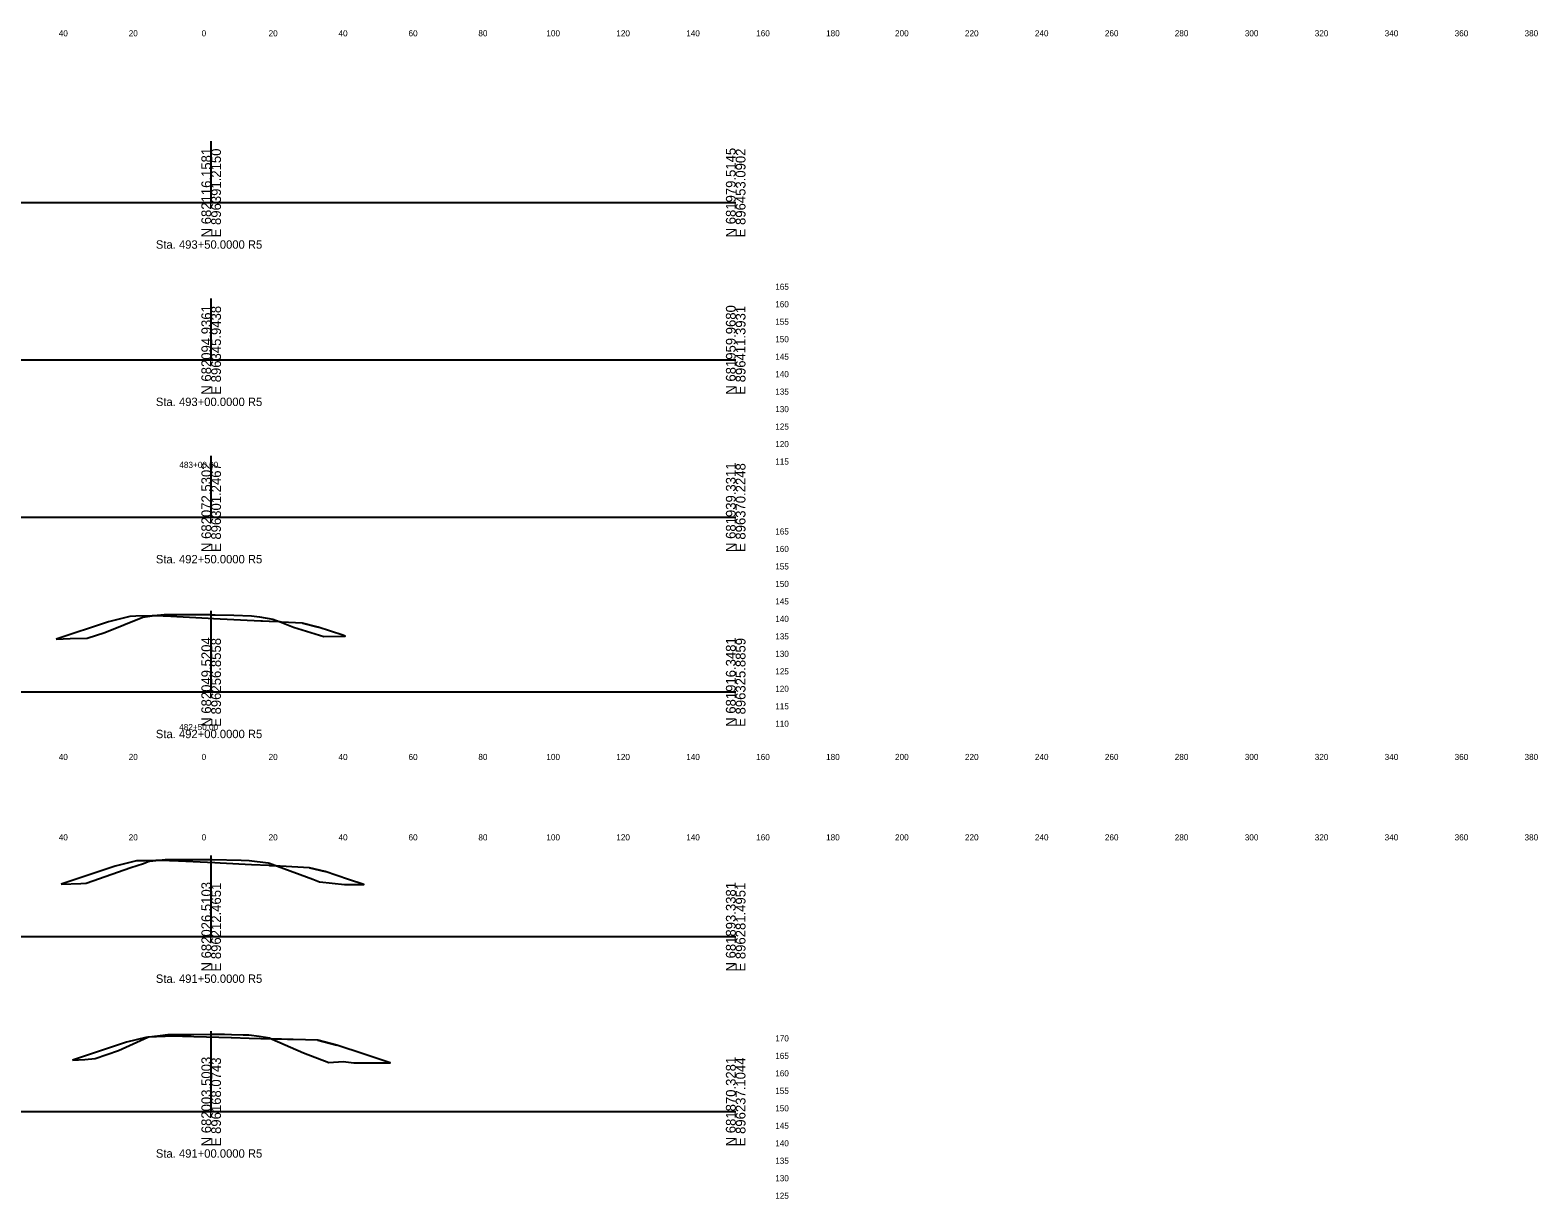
# Model space of a CAD drawing. Extents: x 21059 to 22955, y 6470 to 17494.
# Drawn here: x 21593.1 to 22024.2, y 13019.8 to 13354.1 of the extents above; entities that cross this region are included whole.
import ezdxf

# ---------------------------------------------------------------- set-up
doc = ezdxf.new("R2010")
doc.units = 0
for name, color, linetype in [('Draft_XS_Grid', 7, 'Continuous'), ('Draft_XS_Text', 7, 'Continuous'), ('DTM CONTOURS_MAJOR', 7, 'Continuous'), ('SLOPE_STAKES_FILL', 7, 'Continuous'), ('X_PROFILES_1', 7, 'Continuous'), ('XS_P_GROUND_B', 7, 'Continuous'), ('XS_P_TX_CLEARZONE', 7, 'Continuous'), ('XS_SHEET_EW_TX_VOLUME', 7, 'Continuous')]:
    doc.layers.add(name, color=color, linetype=linetype)

msp = doc.modelspace()

# ---------------------------------------------------------------- linework, layer by layer
at = {"layer": 'DTM CONTOURS_MAJOR'}
for p, q in [((21644.84, 13304.84), (21644.84, 13322.36)), ((21494.84, 13304.84), (21644.84, 13304.84)), ((21644.84, 13304.84), (21794.84, 13304.84)), ((21644.84, 13259.84), (21644.84, 13277.36)), ((21494.84, 13259.84), (21644.84, 13259.84)), ((21644.84, 13259.84), (21794.84, 13259.84)), ((21644.84, 13214.84), (21644.84, 13232.36)), ((21494.84, 13214.84), (21644.84, 13214.84)), ((21644.84, 13214.84), (21794.84, 13214.84)), ((21644.84, 13164.84), (21644.84, 13188.01)), ((21494.84, 13164.84), (21644.84, 13164.84)), ((21644.84, 13164.84), (21794.84, 13164.84)), ((21644.84, 13094.84), (21644.84, 13118.06)), ((21494.84, 13094.84), (21644.84, 13094.84)), ((21644.84, 13094.84), (21794.84, 13094.84)), ((21644.84, 13044.84), (21644.84, 13067.78)), ((21494.84, 13044.84), (21644.84, 13044.84)), ((21644.84, 13044.84), (21794.84, 13044.84))]:
    msp.add_line(p, q, dxfattribs=at)
at = {"layer": 'XS_P_TX_CLEARZONE'}
for points in [[(21621.55, 13186.42), (21615.46, 13184.89)], [(21621.55, 13186.42), (21615.46, 13184.89)], [(21670.98, 13184.5), (21675.48, 13183.37)], [(21670.98, 13184.5), (21675.48, 13183.37)], [(21623.48, 13116.46), (21617.39, 13114.93)], [(21623.48, 13116.46), (21617.39, 13114.93)], [(21672.96, 13114.54), (21677.47, 13113.42)], [(21672.96, 13114.54), (21677.47, 13113.42)], [(21626.14, 13066.01), (21620.59, 13064.62)], [(21626.14, 13066.01), (21620.59, 13064.62)], [(21675.3, 13065.16), (21680.74, 13063.8)], [(21675.3, 13065.16), (21680.74, 13063.8)]]:
    msp.add_lwpolyline(points, dxfattribs=at)
at = {"layer": 'XS_SHEET_EW_TX_VOLUME'}
for points in [[(21600.54, 13179.92), (21604.47, 13180.05), (21609.41, 13180.2), (21614.41, 13181.78), (21625.3, 13186.18), (21628, 13186.54), (21623.26, 13186.45), (21621.55, 13186.42), (21615.46, 13184.89)], [(21628, 13186.54), (21629.53, 13186.75), (21631.37, 13186.95), (21641.61, 13186.92), (21644.93, 13186.94), (21645.04, 13186.9), (21645.94, 13186.9), (21651.31, 13186.75), (21656.39, 13186.59), (21658.63, 13186.29), (21662.43, 13185.62), (21664.57, 13184.82), (21661.48, 13184.97), (21661.44, 13184.98), (21659.48, 13185.07), (21659.04, 13185.1), (21645.47, 13185.77), (21643.94, 13185.85), (21631.47, 13186.47), (21631.12, 13186.49), (21629.47, 13186.57)], [(21664.57, 13184.82), (21668.42, 13183.38), (21677.04, 13180.64), (21683.18, 13180.81), (21682.46, 13181.05), (21675.48, 13183.37), (21670.98, 13184.5), (21664.96, 13184.8)], [(21601.95, 13109.8), (21607.53, 13109.98), (21609.11, 13110.09), (21621.82, 13114.63), (21625.48, 13115.78), (21626.81, 13116.32), (21627.32, 13116.39), (21629.02, 13116.57), (21625.99, 13116.51), (21623.48, 13116.46), (21617.39, 13114.93)], [(21629.02, 13116.57), (21631.68, 13116.85), (21632.85, 13116.84), (21644.67, 13116.9), (21644.69, 13116.9), (21645.1, 13116.9), (21653.39, 13116.71), (21655.67, 13116.64), (21661.09, 13115.91), (21661.53, 13115.83), (21663.76, 13115), (21663.45, 13115.02), (21661.59, 13115.11), (21661.45, 13115.12), (21656.37, 13115.37), (21647.43, 13115.82), (21645.9, 13115.89), (21633.41, 13116.52), (21632.92, 13116.54), (21631.41, 13116.62)], [(21663.76, 13115), (21673.88, 13111.22), (21675.82, 13110.49), (21675.9, 13110.49), (21682.94, 13109.76), (21684.42, 13109.76), (21688.49, 13109.75), (21684.15, 13111.19), (21677.47, 13113.42), (21672.96, 13114.54), (21664.54, 13114.96)], [(21605.16, 13059.5), (21606.85, 13059.56), (21608.69, 13059.71), (21611.7, 13059.94), (21618.32, 13062.29), (21626.73, 13066.03), (21626.14, 13066.01), (21620.59, 13064.62)], [(21626.73, 13066.03), (21627.04, 13066.16), (21629.45, 13066.42), (21632.44, 13066.78), (21639.11, 13066.82), (21644.63, 13066.96), (21648.67, 13066.92), (21650.66, 13066.86), (21653.97, 13066.73), (21655.58, 13066.72), (21658.59, 13066.31), (21661.48, 13065.88), (21662.28, 13065.52), (21655.71, 13065.71), (21650.67, 13065.86), (21650.67, 13065.86), (21639.84, 13066.17), (21636.63, 13066.27), (21635.22, 13066.32), (21634.62, 13066.34), (21631.7, 13066.22)], [(21662.28, 13065.52), (21671.25, 13061.59), (21678.46, 13058.86), (21682.55, 13059.07), (21685.63, 13058.75), (21695.99, 13058.74), (21688.63, 13061.19), (21680.74, 13063.8), (21675.3, 13065.16), (21668.25, 13065.36), (21666.71, 13065.4), (21664.97, 13065.45), (21664.7, 13065.45)]]:
    msp.add_lwpolyline(points, close=True, dxfattribs=at)

# ---------------------------------------------------------------- texts
at = {"layer": 'Draft_XS_Grid'}
for s, p in [('  165  ', (21804.84, 13279.84)), ('  160  ', (21804.84, 13274.84)), ('  155  ', (21804.84, 13269.84)), ('  150  ', (21804.84, 13264.84)), ('  145  ', (21804.84, 13259.84)), ('  140  ', (21804.84, 13254.84)), ('  135  ', (21804.84, 13249.84)), ('  130  ', (21804.84, 13244.84)), ('  125  ', (21804.84, 13239.84)), ('  120  ', (21804.84, 13234.84)), ('  115  ', (21804.84, 13229.84)), ('  165  ', (21804.84, 13209.84)), ('  160  ', (21804.84, 13204.84)), ('  155  ', (21804.84, 13199.84)), ('  150  ', (21804.84, 13194.84)), ('  145  ', (21804.84, 13189.84)), ('  140  ', (21804.84, 13184.84)), ('  135  ', (21804.84, 13179.84)), ('  130  ', (21804.84, 13174.84)), ('  125  ', (21804.84, 13169.84)), ('  120  ', (21804.84, 13164.84)), ('  115  ', (21804.84, 13159.84)), ('  110  ', (21804.84, 13154.84)), ('  170  ', (21804.84, 13064.84)), ('  165  ', (21804.84, 13059.84)), ('  160  ', (21804.84, 13054.84)), ('  155  ', (21804.84, 13049.84)), ('  150  ', (21804.84, 13044.84)), ('  145  ', (21804.84, 13039.84)), ('  140  ', (21804.84, 13034.84)), ('  135  ', (21804.84, 13029.84)), ('  130  ', (21804.84, 13024.84)), ('  125  ', (21804.84, 13019.84))]:
    msp.add_text(s, height=1.75, dxfattribs=at).set_placement(p)
at = {"layer": 'Draft_XS_Text'}
for s, p in [('  40  ', (21599.95, 13352.34)), ('  20  ', (21619.95, 13352.34)), ('  0  ', (21640.81, 13352.34)), ('  0  ', (21640.81, 13352.34)), ('  20  ', (21659.95, 13352.34)), ('  40  ', (21679.95, 13352.34)), ('  60  ', (21699.97, 13352.34)), ('  80  ', (21719.95, 13352.34)), ('  100  ', (21739.39, 13352.34)), ('  120  ', (21759.39, 13352.34)), ('  140  ', (21779.39, 13352.34)), ('  160  ', (21799.4, 13352.34)), ('  180  ', (21819.39, 13352.34)), ('  200  ', (21839.1, 13352.34)), ('  220  ', (21859.1, 13352.34)), ('  240  ', (21879.1, 13352.34)), ('  260  ', (21899.11, 13352.34)), ('  280  ', (21919.1, 13352.34)), ('  300  ', (21939.13, 13352.34)), ('  320  ', (21959.13, 13352.34)), ('  340  ', (21979.13, 13352.34)), ('  360  ', (21999.14, 13352.34)), ('  380  ', (22019.13, 13352.34)), ('  40  ', (21599.95, 13145.34)), ('  20  ', (21619.95, 13145.34)), ('  0  ', (21640.81, 13145.34)), ('  0  ', (21640.81, 13145.34)), ('  20  ', (21659.95, 13145.34)), ('  40  ', (21679.95, 13145.34)), ('  60  ', (21699.97, 13145.34)), ('  80  ', (21719.95, 13145.34)), ('  100  ', (21739.39, 13145.34)), ('  120  ', (21759.39, 13145.34)), ('  140  ', (21779.39, 13145.34)), ('  160  ', (21799.4, 13145.34)), ('  180  ', (21819.39, 13145.34)), ('  200  ', (21839.1, 13145.34)), ('  220  ', (21859.1, 13145.34)), ('  240  ', (21879.1, 13145.34)), ('  260  ', (21899.11, 13145.34)), ('  280  ', (21919.1, 13145.34)), ('  300  ', (21939.13, 13145.34)), ('  320  ', (21959.13, 13145.34)), ('  340  ', (21979.13, 13145.34)), ('  360  ', (21999.14, 13145.34)), ('  380  ', (22019.13, 13145.34)), ('  40  ', (21599.95, 13122.34)), ('  20  ', (21619.95, 13122.34)), ('  0  ', (21640.81, 13122.34)), ('  0  ', (21640.81, 13122.34)), ('  20  ', (21659.95, 13122.34)), ('  40  ', (21679.95, 13122.34)), ('  60  ', (21699.97, 13122.34)), ('  80  ', (21719.95, 13122.34)), ('  100  ', (21739.39, 13122.34)), ('  120  ', (21759.39, 13122.34)), ('  140  ', (21779.39, 13122.34)), ('  160  ', (21799.4, 13122.34)), ('  180  ', (21819.39, 13122.34)), ('  200  ', (21839.1, 13122.34)), ('  220  ', (21859.1, 13122.34)), ('  240  ', (21879.1, 13122.34)), ('  260  ', (21899.11, 13122.34)), ('  280  ', (21919.1, 13122.34)), ('  300  ', (21939.13, 13122.34)), ('  320  ', (21959.13, 13122.34)), ('  340  ', (21979.13, 13122.34)), ('  360  ', (21999.14, 13122.34)), ('  380  ', (22019.13, 13122.34))]:
    msp.add_text(s, height=1.75, dxfattribs=at).set_placement(p)
at = {"layer": 'DTM CONTOURS_MAJOR'}
for s, p in [('N 682116.1581', (21644.84, 13294.84)), ('E 896391.2150', (21647.64, 13294.84)), ('N 681979.5145', (21794.84, 13294.84)), ('E 896453.0902', (21797.64, 13294.84)), ('N 682094.9361', (21644.84, 13249.84)), ('E 896345.9438', (21647.64, 13249.84)), ('N 681959.9680', (21794.84, 13249.84)), ('E 896411.3931', (21797.64, 13249.84)), ('N 682072.5302', (21644.84, 13204.84)), ('E 896301.2467', (21647.64, 13204.84)), ('N 681939.3311', (21794.84, 13204.84)), ('E 896370.2248', (21797.64, 13204.84)), ('N 682049.5204', (21644.84, 13154.84)), ('E 896256.8558', (21647.64, 13154.84)), ('N 681916.3481', (21794.84, 13154.84)), ('E 896325.8859', (21797.64, 13154.84)), ('N 682026.5103', (21644.84, 13084.84)), ('E 896212.4651', (21647.64, 13084.84)), ('N 681893.3381', (21794.84, 13084.84)), ('E 896281.4951', (21797.64, 13084.84)), ('N 682003.5003', (21644.84, 13034.84)), ('N 681870.3281', (21794.84, 13034.84)), ('E 896168.0743', (21647.64, 13034.84)), ('E 896237.1044', (21797.64, 13034.84))]:
    msp.add_text(s, height=2.8, rotation=90, dxfattribs=at).set_placement(p)
at = {"layer": 'SLOPE_STAKES_FILL'}
for s, p in [('  483+00.00  ', (21634.43, 13228.89)), ('  482+50.00  ', (21634.4, 13153.89))]:
    msp.add_text(s, height=1.75, dxfattribs=at).set_placement(p)
at = {"layer": 'X_PROFILES_1'}
for s, p in [('Sta. 493+50.0000 R5', (21629.02, 13291.59)), ('Sta. 493+00.0000 R5', (21629.02, 13246.59)), ('Sta. 492+50.0000 R5', (21629.02, 13201.59)), ('Sta. 492+00.0000 R5', (21629.02, 13151.59)), ('Sta. 491+50.0000 R5', (21629.02, 13081.59)), ('Sta. 491+00.0000 R5', (21629.02, 13031.59))]:
    msp.add_text(s, height=2.4, dxfattribs=at).set_placement(p)
at = {"layer": 'XS_P_GROUND_B'}
for p in [(21600.5, 13179.86), (21600.5, 13179.86), (21683.14, 13180.75), (21683.14, 13180.75), (21601.91, 13109.74), (21601.91, 13109.74), (21688.45, 13109.69), (21688.45, 13109.69), (21605.12, 13059.44), (21605.12, 13059.44), (21695.95, 13058.68), (21695.95, 13058.68)]:
    msp.add_text('X', height=0.12, dxfattribs=at).set_placement(p)

doc.saveas('drawing.dxf')
